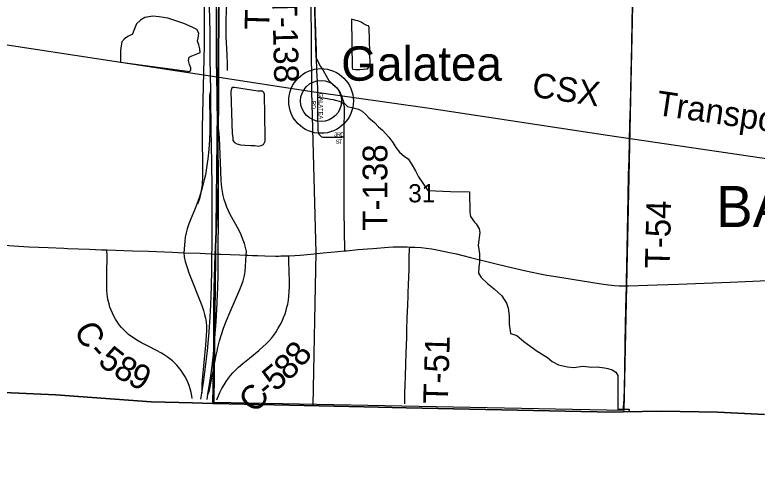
# Model space of a CAD drawing. Extents: x 1443599 to 1910620, y 1028088 to 1361369.
# Drawn here: x 1649524 to 1658538, y 1154990 to 1160667 of the extents above; entities that cross this region are included whole.
import ezdxf

# ---------------------------------------------------------------- set-up
doc = ezdxf.new("R2010")
doc.units = 0
for name, color, linetype in [('GM_X_Adjacent_County', 7, 'Continuous'), ('GM_X_Corporation_Text', 7, 'Continuous'), ('GM_X_County', 7, 'Continuous'), ('GM_X_County_Road', 7, 'Continuous'), ('GM_X_County_Road_Text', 7, 'Continuous'), ('GM_X_Interchange_Ramps', 7, 'Continuous'), ('GM_X_Interstate_Route', 7, 'Continuous'), ('GM_X_Minor_Lake', 7, 'Continuous'), ('GM_X_Minor_River', 7, 'Continuous'), ('GM_X_Rail_Line', 7, 'Continuous'), ('GM_X_Rail_Line_Text', 7, 'Continuous'), ('GM_X_Section', 7, 'Continuous'), ('GM_X_Section_Text', 7, 'Continuous'), ('GM_X_State_Route', 7, 'Continuous'), ('GM_X_Township', 7, 'Continuous'), ('GM_X_Township_Road', 7, 'Continuous'), ('GM_X_Township_Road_Text', 7, 'Continuous'), ('GM_X_Township_Subdivision', 7, 'Continuous'), ('GM_X_Township_Subdivision_Text', 7, 'Continuous'), ('GM_X_Unincorporated', 7, 'Continuous'), ('GM_X_Unincorporated_Location', 7, 'Continuous'), ('GM_X_Unincorporated_Text', 7, 'Continuous')]:
    doc.layers.add(name, color=color, linetype=linetype)

msp = doc.modelspace()

# ---------------------------------------------------------------- linework, layer by layer
at = {"layer": 'GM_X_Adjacent_County'}
msp.add_lwpolyline([(1631321.7, 1156526.4), (1635964.6, 1156489.9), (1636394.3, 1156486.5), (1639893.6, 1156408.7), (1641054, 1156382.8), (1641985.5, 1156362.1), (1643814, 1156287.4), (1643986.6, 1156280.4), (1645977.2, 1156199.2), (1648123.1, 1156134), (1650022.7, 1156050.6), (1651177.8, 1155965), (1651682.5, 1155953.3), (1651801.4, 1155950.6), (1651929.8, 1155947.6), (1651945.1, 1155947.3), (1653765.2, 1155905.3), (1654275.8, 1155894.5), (1656788.7, 1155841.5), (1656910.1, 1155843.6), (1657377.2, 1155851.8), (1658061.8, 1155840.1), (1658626.2, 1155812.7)], dxfattribs=at)
at = {"layer": 'GM_X_County'}
msp.add_lwpolyline([(1658626.2, 1155812.7), (1658061.8, 1155840.1), (1657377.2, 1155851.8), (1656910.1, 1155843.6), (1656788.7, 1155841.5), (1654275.8, 1155894.5), (1653765.2, 1155905.3), (1651945.1, 1155947.3), (1651929.8, 1155947.6), (1651801.4, 1155950.6), (1651682.5, 1155953.3), (1651177.8, 1155965), (1650022.7, 1156050.6), (1648123.1, 1156134), (1645977.2, 1156199.2), (1643986.6, 1156280.4), (1643814, 1156287.4), (1641985.5, 1156362.1), (1641054, 1156382.8), (1639893.6, 1156408.7), (1636394.3, 1156486.5), (1635964.6, 1156489.9), (1631321.7, 1156526.4)], dxfattribs=at)
at = {"layer": 'GM_X_County_Road'}
for points in [[(1650643, 1157427.7), (1650642.7, 1157563.4), (1650644.3, 1157702.8), (1650643.8, 1157744), (1650643.1, 1157811.6)], [(1651977.1, 1155989.1), (1651983.9, 1156009.9), (1651995.9, 1156040.7), (1652013.3, 1156078), (1652039.8, 1156129.2), (1652064.2, 1156172.1), (1652090.9, 1156213.7), (1652119.3, 1156254.1), (1652144.6, 1156286.6), (1652171.6, 1156317.8), (1652200.1, 1156347.5), (1652241.9, 1156387.1), (1652291.2, 1156430.5), (1652373.6, 1156498.3), (1652488.3, 1156590.9), (1652537.3, 1156634.1), (1652578.8, 1156673.4), (1652612.8, 1156708.6), (1652645, 1156745.4), (1652670.1, 1156777.5), (1652698, 1156817.6), (1652723.8, 1156859.2), (1652747.4, 1156902), (1652769, 1156945.9), (1652788.5, 1156990.8), (1652805.8, 1157036.5), (1652818.4, 1157075.3), (1652829.2, 1157114.5), (1652838.1, 1157154.3), (1652846.2, 1157202.5), (1652852.2, 1157251.1), (1652856.6, 1157308.1), (1652858.7, 1157365.2), (1652858.8, 1157430.6), (1652855.1, 1157545.1), (1652850.3, 1157676.2), (1652850.1, 1157741)], [(1651678.4, 1156007), (1651673, 1156037.3), (1651664.5, 1156077.7), (1651651.9, 1156125.6), (1651639.2, 1156164.8), (1651624.3, 1156203.4), (1651607, 1156240.9), (1651587.4, 1156277.3), (1651566, 1156312.5), (1651542.7, 1156346.6), (1651512.5, 1156386), (1651490.9, 1156411), (1651468.1, 1156434.9), (1651437.9, 1156463.1), (1651406.1, 1156489.5), (1651372.9, 1156514.1), (1651338.6, 1156537), (1651303.3, 1156558.3), (1651245.5, 1156589.8), (1651143.3, 1156642.4), (1651055.8, 1156687.3), (1651005.9, 1156715.4), (1650964.4, 1156741.4), (1650931.1, 1156764.9), (1650905.6, 1156785), (1650881, 1156806.4), (1650851.7, 1156834.7), (1650818.4, 1156870.6), (1650792.7, 1156902.1), (1650769, 1156935.3), (1650747.3, 1156969.8), (1650727.4, 1157005.3), (1650709.5, 1157041.9), (1650693.7, 1157079.5), (1650679.8, 1157117.8), (1650667.9, 1157156.8), (1650658.1, 1157196.4), (1650650.6, 1157236.4), (1650645.7, 1157276.8), (1650643.3, 1157317.4), (1650643.2, 1157366.5), (1650643, 1157427.7)]]:
    msp.add_lwpolyline(points, dxfattribs=at)
at = {"layer": 'GM_X_Interchange_Ramps'}
for points in [[(1651902.3, 1159748.6), (1651897.5, 1159730.1), (1651891.6, 1159707.8), (1651888.4, 1159686.3), (1651886.4, 1159659.1), (1651887.3, 1159622.2), (1651891.3, 1159410), (1651890.8, 1159262), (1651886.4, 1159146.9), (1651878.5, 1159032.1), (1651867.1, 1158917.6), (1651856.6, 1158836), (1651839.6, 1158725), (1651825.3, 1158664.3), (1651811.8, 1158614), (1651790.4, 1158538), (1651761.8, 1158443.6), (1651734.6, 1158367.5), (1651704.8, 1158292.5), (1651659.5, 1158187.3), (1651636.5, 1158126.9), (1651615.9, 1158066.4), (1651603.4, 1158017.7), (1651594.6, 1157968.2), (1651588.9, 1157918.3), (1651576, 1157776.8)], [(1652334.4, 1157746.9), (1652335.9, 1157793.8), (1652333.6, 1157810.1), (1652326.2, 1157842), (1652312.1, 1157889.2), (1652290.2, 1157951.1), (1652271.3, 1157996.6), (1652242.7, 1158055.7), (1652140.6, 1158243.1), (1652118.5, 1158287.2), (1652098.5, 1158332.1), (1652081.2, 1158378.2), (1652066.3, 1158425.2), (1652054.2, 1158472.9), (1652044.8, 1158521.2), (1652037.7, 1158570), (1652030.6, 1158651.8), (1652025, 1158766.5), (1652009, 1159172.8), (1652005.9, 1159222), (1652002.5, 1159257.6), (1651997.2, 1159295), (1651986.8, 1159348)], [(1651576, 1157776.8), (1651579.2, 1157727.7), (1651591.9, 1157672.3), (1651611.2, 1157609.9), (1651638.8, 1157533), (1651794.3, 1157137.4), (1651815.8, 1157075.6), (1651828.9, 1157028.5), (1651838.8, 1156980.4), (1651845.7, 1156931.9), (1651849.7, 1156883.1), (1651850.6, 1156834.1), (1651848.3, 1156768.7), (1651839.7, 1156654.5), (1651798.1, 1156231.6), (1651795.1, 1156190.3), (1651793.4, 1156137.4), (1651795, 1156071.2)], [(1651869, 1156056.6), (1651880.5, 1156081.8), (1651885.7, 1156094.9), (1651889.8, 1156109.2), (1651945.4, 1156402.3), (1651969.7, 1156531), (1651980.6, 1156580.5), (1651990.8, 1156627), (1652011.1, 1156706.2), (1652034.2, 1156784.8), (1652060.1, 1156862.5), (1652094.3, 1156954.5), (1652138, 1157060.5), (1652255.8, 1157330.7), (1652280.4, 1157391.4), (1652296.6, 1157437.7), (1652305.6, 1157469.2), (1652312.7, 1157501.1), (1652320.6, 1157549.5), (1652326.4, 1157614.7), (1652330.4, 1157680.1), (1652334.4, 1157746.9)]]:
    msp.add_lwpolyline(points, dxfattribs=at)
at = {"layer": 'GM_X_Interstate_Route'}
for points in [[(1651974.6, 1160049.3), (1651973.4, 1160186.6), (1651972, 1160498.4), (1651971.2, 1160728.2), (1651973.4, 1161039.9), (1651974.7, 1161285.4), (1651975.2, 1161368.1), (1651976.4, 1161473.3), (1651982.7, 1162040.8), (1651983.8, 1162352.5), (1651985.4, 1162591.9)], [(1651784.4, 1155999.6), (1651795, 1156071.2), (1651817.5, 1156227.3), (1651839.9, 1156389.9), (1651862.1, 1156585.7), (1651883.5, 1156814.6), (1651897.4, 1156994.7), (1651905.8, 1157142.3), (1651913.7, 1157372), (1651917, 1157569), (1651916.9, 1157733), (1651917.6, 1157764.6), (1651918.6, 1157815.1), (1651920.5, 1158077.6), (1651921.9, 1158291.1), (1651920.1, 1158570.1), (1651914.7, 1158865.4), (1651910, 1159292), (1651903.1, 1159653), (1651902.3, 1159748.6), (1651900.9, 1159932), (1651898.1, 1160145.4), (1651894.2, 1160457.1), (1651889.6, 1160768.9)], [(1651997, 1158390.5), (1651997.2, 1158496.6), (1651993.5, 1158923.1), (1651986.8, 1159348), (1651986.5, 1159366.1), (1651982.5, 1159628.6), (1651975.2, 1159973.2), (1651974.6, 1160049.3)], [(1651994.4, 1157718.7), (1651994.4, 1157725.3), (1651994.6, 1157761.2), (1651995.3, 1157922.3), (1651996.5, 1158070), (1651997, 1158390.5)], [(1651987.1, 1157274.4), (1651990.1, 1157348.1), (1651993.3, 1157528.5), (1651994.4, 1157718.7)], [(1651858.7, 1155994.9), (1651869, 1156056.6), (1651899.3, 1156253.4), (1651919.1, 1156399.7), (1651935.5, 1156546.3), (1651958.7, 1156791.3), (1651969.8, 1156938.5), (1651982.9, 1157167.8), (1651987.1, 1157274.4)]]:
    msp.add_lwpolyline(points, dxfattribs=at)
at = {"layer": 'GM_X_Minor_Lake'}
for p, q in [((1653613.2, 1160613.1), (1653620.3, 1160023.4)), ((1650806.1, 1160093.6), (1651651.3, 1159979.3)), ((1652476.7, 1159741), (1652191, 1159783.1))]:
    msp.add_line(p, q, dxfattribs=at)
for points in [[(1651651.3, 1159979.3), (1651661.6, 1159997.2), (1651660, 1160023.3), (1651646.6, 1160063.6), (1651633.4, 1160113.9), (1651639.9, 1160151.9), (1651674.2, 1160167.5), (1651718.5, 1160184.9), (1651775, 1160210.2), (1651771.6, 1160254.3), (1651758.3, 1160302.6), (1651743, 1160349), (1651749.5, 1160383), (1651760.5, 1160443), (1651735.1, 1160489.5), (1651679.5, 1160518.3), (1651576.1, 1160563.9), (1651492.4, 1160589.2), (1651380.8, 1160628.9), (1651274.9, 1160642.4), (1651199, 1160651.5), (1651102.6, 1160636.9), (1651052.1, 1160603.5), (1651001.3, 1160556.1), (1650976.3, 1160496.3), (1650961.7, 1160456.4), (1650951.4, 1160432.5), (1650894.9, 1160403.2), (1650854.4, 1160375.7), (1650821.8, 1160340.1), (1650815.1, 1160292), (1650808.2, 1160236), (1650806.1, 1160093.6)], [(1653620.3, 1160023.4), (1653626.1, 1160007.3), (1653662.1, 1160002.8), (1653714, 1160004), (1653756.2, 1160007.5), (1653806.4, 1160012.8), (1653832.8, 1160040.5), (1653839.1, 1160060.4), (1653826, 1160513.8), (1653818.2, 1160532), (1653800.3, 1160536.2), (1653766.5, 1160552.8), (1653730.8, 1160579.3), (1653691, 1160593.9), (1653665.1, 1160600.3), (1653613.2, 1160613.1)], [(1652191, 1159783.1), (1652173, 1159783.4), (1652156.8, 1159771.6), (1652146.3, 1159737.6), (1652164.5, 1159222), (1652171.9, 1159177.8), (1652173.3, 1159139.7), (1652191.3, 1159116), (1652218.8, 1159100.9), (1652262.6, 1159086.3), (1652320.7, 1159085.4), (1652390.7, 1159080.4), (1652438.7, 1159081.8), (1652482.7, 1159073.1), (1652516.8, 1159078.6), (1652543, 1159092.3), (1652563.6, 1159132.1), (1652564.5, 1159186.2), (1652556.2, 1159701.7), (1652547.5, 1159724.3), (1652530.7, 1159738.2), (1652476.7, 1159741)]]:
    msp.add_lwpolyline(points, dxfattribs=at)
at = {"layer": 'GM_X_Minor_River'}
for points in [[(1651631.1, 1165306.8), (1651741.3, 1164983.8), (1651761.2, 1164468.2), (1651757.1, 1163998.8), (1651606.7, 1163615.7), (1651456.4, 1163246.7), (1651446.1, 1162337.9), (1651434, 1161690), (1651427.9, 1161220.6), (1651824.5, 1161196.5), (1651822.3, 1160299.7), (1651800.1, 1159298.6), (1651804.1, 1158702.8), (1651800, 1158602.5), (1651784, 1158510.2), (1651768, 1158431.9), (1651743.9, 1158365.7)], [(1653150.7, 1161142.1), (1653178.5, 1160147.1), (1653234.6, 1160038.8), (1653264.7, 1160000.6), (1653304.7, 1159924.4), (1653338.8, 1159870.2), (1653380.8, 1159826.1), (1653428.9, 1159784), (1653469, 1159731.8), (1653497, 1159665.6), (1653521, 1159597.4), (1653565.1, 1159553.2), (1653631.2, 1159539.2), (1653699.3, 1159521.1), (1653743.4, 1159497), (1653787.4, 1159454.9), (1653823.5, 1159414.8), (1653891.6, 1159358.6), (1653939.7, 1159306.4), (1653989.7, 1159266.3), (1654067.8, 1159180), (1654113.9, 1159115.8), (1654150, 1159057.6), (1654196, 1158999.4), (1654256.1, 1158945.3), (1654302.2, 1158917.2), (1654338.3, 1158861), (1654388.3, 1158772.7), (1654424.4, 1158698.5), (1654538.5, 1158533.9), (1654813, 1158521.9), (1655043.4, 1158517.8), (1655051.3, 1158265), (1655057.4, 1158216.9), (1655105.4, 1158146.6), (1655127.5, 1158126.6), (1655163.5, 1158066.4), (1655171.5, 1158022.2), (1655149.5, 1157867.8), (1655165.5, 1157763.4), (1655165.5, 1157663.1), (1655159.4, 1157606.9), (1655153.4, 1157528.7), (1655187.5, 1157476.5), (1655265.6, 1157402.3), (1655345.7, 1157340.1), (1655439.9, 1157253.8), (1655494, 1157165.5), (1655516, 1157103.3), (1655526, 1157009), (1655526, 1156910.7), (1655538, 1156826.4), (1655542, 1156796.3), (1655620.1, 1156772.2), (1655706.3, 1156698), (1655794.4, 1156635.8), (1655866.5, 1156579.6), (1655990.7, 1156503.3), (1656050.8, 1156457.1), (1656126.9, 1156417), (1656235.1, 1156390.9), (1656313.2, 1156384.9), (1656421.4, 1156398.9), (1656529.6, 1156386.9), (1656593.7, 1156390.9), (1656685.9, 1156380.8), (1656725.9, 1156370.8), (1656778, 1156352.7), (1656824.1, 1156324.6), (1656848.1, 1156284.5), (1656848.1, 1156222.3), (1656846.1, 1155877.2), (1656982.3, 1155875.2), (1656981.1, 1155847.1)]]:
    msp.add_lwpolyline(points, dxfattribs=at)
at = {"layer": 'GM_X_Rail_Line'}
for points in [[(1653131.7, 1159734.3), (1653131.5, 1159774.4), (1653117.5, 1161384.9), (1653128.4, 1163893.8), (1653262.4, 1169152.8), (1653341.6, 1175752.4), (1653359.9, 1180304.5), (1653421.3, 1187177.3), (1653422.3, 1187382.1)], [(1645299.4, 1160898), (1647993, 1160519.8), (1651978.5, 1159912.5)], [(1651978.5, 1159912.5), (1653131.7, 1159734.3)], [(1653147.8, 1155927.1), (1653183.2, 1157781.6), (1653131.7, 1159734.3)], [(1653131.7, 1159734.3), (1654559.8, 1159532.2), (1656720, 1159206.3), (1661518.7, 1158502.4), (1663430.3, 1158232.7), (1665610.5, 1157902.5), (1670331.1, 1157208.4), (1674785.3, 1156557.2), (1678092.3, 1156076.4), (1685476.1, 1154990)]]:
    msp.add_lwpolyline(points, dxfattribs=at)
at = {"layer": 'GM_X_Section'}
msp.add_lwpolyline([(1657034.3, 1161164.9), (1656920.5, 1155860.4), (1651946.1, 1155956.1), (1652006.2, 1161276.9)], close=True, dxfattribs=at)
at = {"layer": 'GM_X_State_Route'}
for points in [[(1649279.5, 1157881.9), (1649305.8, 1157879.4), (1649449.8, 1157866.7), (1649694.2, 1157849.8), (1649930.7, 1157838.9), (1650119.3, 1157831.9), (1650164.6, 1157830.1)], [(1650164.6, 1157830.1), (1650430.4, 1157819.6)], [(1650430.4, 1157819.6), (1650576.2, 1157813.8), (1650643.1, 1157811.6), (1650951.4, 1157801.4), (1651147.3, 1157795.2), (1651440.2, 1157782.6), (1651576, 1157776.8), (1651775.2, 1157770.5), (1651834.3, 1157768.3), (1651835.7, 1157768.3)], [(1651835.7, 1157768.3), (1651917.6, 1157764.6), (1651994.6, 1157761.2), (1652024.9, 1157759.9), (1652252.2, 1157749.9), (1652334.4, 1157746.9)], [(1652850.1, 1157741), (1652924.5, 1157744.9), (1652990.4, 1157749.6), (1653119.6, 1157760.4), (1653195.6, 1157766.7), (1653231.2, 1157771.2), (1653266.9, 1157774.9), (1653361.6, 1157784.1), (1653531.7, 1157800.5), (1653551.1, 1157802.3), (1653694.9, 1157816.2), (1653806.1, 1157825)], [(1653806.1, 1157825), (1653871.5, 1157830.1), (1654061.3, 1157845.4), (1654120.2, 1157848.1), (1654181.7, 1157849.4), (1654290.4, 1157847.7), (1654319, 1157846.6), (1654382.2, 1157844.3), (1654457.4, 1157839.3), (1654519.2, 1157833), (1654587.2, 1157823.2), (1654667.9, 1157808.8), (1654803, 1157781.7), (1654886.2, 1157763.2), (1654962.5, 1157744), (1655058, 1157720), (1655351.1, 1157647.1), (1655501.3, 1157611.5), (1655728.5, 1157559.2), (1655882.5, 1157525.5), (1655982.5, 1157506), (1656118.6, 1157483), (1656293.8, 1157456), (1656517.2, 1157418.6), (1656643.8, 1157399.1), (1656735, 1157386.9), (1656807.1, 1157379.8), (1656863, 1157376.3), (1656950.1, 1157375.5), (1656977.4, 1157376.2), (1657322.4, 1157385.3), (1657585.1, 1157393.4), (1657897, 1157406.6), (1658209, 1157421.3), (1658668.8, 1157439.2)], [(1652334.4, 1157746.9), (1652356.7, 1157746), (1652412.3, 1157743.4), (1652470.5, 1157742.1), (1652561.1, 1157739.2), (1652689.1, 1157736.7), (1652728.6, 1157737.2), (1652754.9, 1157737.8), (1652850.1, 1157741)]]:
    msp.add_lwpolyline(points, dxfattribs=at)
at = {"layer": 'GM_X_Township'}
for points in [[(1652041.9, 1171813.2), (1652030.8, 1166476.2), (1652008.3, 1163866.7), (1651998.2, 1162695.7), (1651998.9, 1162185.8), (1652000.1, 1161249), (1651996.4, 1159520.9), (1651990.3, 1159208.4), (1651994.9, 1158602.7), (1651958, 1157753.6), (1651943.2, 1157343), (1651941.2, 1157133.4), (1651940.5, 1156563.6), (1651929.8, 1155947.6), (1651801.4, 1155950.6), (1651682.5, 1155953.3), (1651177.8, 1155965), (1650022.7, 1156050.6), (1648123.1, 1156134)], [(1658626.2, 1155812.7), (1658061.8, 1155840.1), (1657377.2, 1155851.8), (1656910.1, 1155843.6), (1656788.7, 1155841.5), (1654275.8, 1155894.5), (1653765.2, 1155905.3), (1651945.1, 1155947.3), (1651929.8, 1155947.6), (1651940.5, 1156563.6), (1651941.2, 1157133.4), (1651943.2, 1157343), (1651958, 1157753.6), (1651994.9, 1158602.7), (1651990.3, 1159208.4), (1651996.4, 1159520.9), (1652000.1, 1161249), (1651998.9, 1162185.8), (1651998.2, 1162695.7), (1652008.3, 1163866.7), (1652030.8, 1166476.2), (1652041.9, 1171813.2)]]:
    msp.add_lwpolyline(points, dxfattribs=at)
at = {"layer": 'GM_X_Township_Road'}
for points in [[(1653205.2, 1159663.4), (1653205.6, 1159685), (1653203.5, 1159782.8), (1653200.4, 1159839.9), (1653195.1, 1159938.1), (1653193.5, 1159970.8), (1653190.1, 1160044.6), (1653187.7, 1160101.9), (1653187.5, 1160224.3), (1653184.2, 1160338.3), (1653180.2, 1160439.5), (1653179.5, 1160483.1), (1653176.7, 1160557.6), (1653172.3, 1160693.5), (1653167, 1160874.6), (1653160.3, 1161068.6), (1653158.1, 1161165.1), (1653157.5, 1161214.3), (1653157.1, 1161239.6)], [(1656950.1, 1157375.5), (1656951.2, 1157426.1), (1656958.6, 1157819.8), (1656971.8, 1158459.6), (1656977.8, 1158722), (1656982.7, 1158918.8), (1656987.9, 1159132), (1656993.1, 1159345.2), (1656998.6, 1159558.4), (1657008.8, 1159952), (1657015.6, 1160296.5), (1657021.7, 1160591.8), (1657029.5, 1160936.2), (1657032.2, 1161116.6), (1657032.7, 1161165.8)], [(1652108, 1159989.9), (1652105.3, 1160063.8), (1652101.2, 1160186.9), (1652090.6, 1160400.2), (1652089.4, 1160465.9), (1652091, 1160580.9), (1652095.1, 1160736.9), (1652096.8, 1160781.5)], [(1653523.1, 1159569.8), (1653518.4, 1159578.1), (1653512.8, 1159585.4), (1653507.3, 1159591.5), (1653501.4, 1159597.1), (1653495, 1159602), (1653487.7, 1159606.6), (1653480.9, 1159610), (1653467.5, 1159615), (1653451.9, 1159619.5), (1653435, 1159624.2), (1653419.6, 1159628.1), (1653395.9, 1159633.2), (1653359.2, 1159640.5), (1653315.2, 1159648), (1653267.1, 1159655.7), (1653226.8, 1159660.7), (1653205.2, 1159663.4)], [(1653521.6, 1159179.3), (1653521.5, 1159195.1), (1653521.8, 1159318.1), (1653526.1, 1159473.8), (1653526.7, 1159539.1), (1653526.1, 1159551.7), (1653525, 1159560.5), (1653523.1, 1159569.8)], [(1653523.5, 1158751), (1653523.6, 1158785.5), (1653525.1, 1158916.7), (1653524.6, 1158998.6), (1653523.5, 1159104.8), (1653521.9, 1159145.3), (1653521.6, 1159179.3)], [(1653531.7, 1157800.5), (1653531, 1157842.7), (1653528.4, 1158006.6), (1653525.1, 1158318.2), (1653522.7, 1158474), (1653523.5, 1158703.5), (1653523.5, 1158751)], [(1654258.6, 1155941.5), (1654259.5, 1155989.3), (1654261.7, 1156064.3), (1654264.9, 1156180.1), (1654268.1, 1156270.2), (1654271.7, 1156426), (1654275.8, 1156557.2), (1654282.7, 1156745.7), (1654285.1, 1156844), (1654289, 1156983.4), (1654295.2, 1157139.1), (1654299.2, 1157253.8), (1654299.7, 1157294.8), (1654302.9, 1157384.1), (1654310.9, 1157580.8), (1654314.5, 1157728.7), (1654318, 1157822.5), (1654319, 1157846.6)], [(1656911.4, 1155874.5), (1656914.4, 1155898.3), (1656919.3, 1155951.3), (1656922.7, 1155999.2), (1656927.5, 1156130.2), (1656931.1, 1156343.4), (1656935.4, 1156688), (1656943.9, 1157098.1), (1656950.1, 1157375.5)]]:
    msp.add_lwpolyline(points, dxfattribs=at)
at = {"layer": 'GM_X_Township_Subdivision'}
for points in [[(1653227.9, 1159204.9), (1653221.8, 1159214.8), (1653218, 1159223), (1653214.1, 1159233.4), (1653211.6, 1159243.2), (1653207.9, 1159267.9), (1653206.8, 1159282.8), (1653205.7, 1159310.9), (1653204.5, 1159408.2), (1653203.7, 1159464.9), (1653204, 1159503.6), (1653204.3, 1159547.1), (1653204.5, 1159580.5), (1653204.8, 1159614.4), (1653205.2, 1159663.4)], [(1653521.6, 1159179.3), (1653494.7, 1159179), (1653455.2, 1159178.6), (1653414.3, 1159178.6), (1653348.1, 1159177), (1653307.2, 1159176.2), (1653282.7, 1159177), (1653268.1, 1159178.9), (1653257.5, 1159181.6), (1653250.1, 1159185.1), (1653243.1, 1159189.4), (1653234.1, 1159197.6), (1653227.9, 1159204.9)]]:
    msp.add_lwpolyline(points, dxfattribs=at)
at = {"layer": 'GM_X_Unincorporated'}
for radius in [392.8, 249]:
    msp.add_circle((1653242.4, 1159620.7), radius, dxfattribs=at)
at = {"layer": 'GM_X_Unincorporated_Location'}
msp.add_line((1653242.4, 1159620.7), (1653242.4, 1159620.7), dxfattribs=at)

# ---------------------------------------------------------------- texts
at = {"layer": 'GM_X_Corporation_Text'}
msp.add_text('BAIRDSTOWN', height=500, rotation=0.00001, dxfattribs=at).set_placement((1658038.8, 1158088.4))
at = {"layer": 'GM_X_County_Road_Text'}
for s, rotation, p in [('C', 298.08374, (1650234.8, 1156843.7)), ('8', 51.78068, (1653011.8, 1156374.3)), ('-', 312.72996, (1650399.2, 1156558.2)), ('5', 321.55071, (1650519.7, 1156433.4)), ('8', 329.78212, (1650703.3, 1156292)), ('8', 43.01807, (1652842.8, 1156211.4)), ('9', 333.10909, (1650879.7, 1156189.9)), ('5', 39.49041, (1652685, 1156080.6)), ('C', 54.93395, (1652464.4, 1155814.4)), ('-', 40.59113, (1652592.6, 1156001.4))]:
    msp.add_text(s, height=300, rotation=rotation, dxfattribs=at).set_placement(p)
at = {"layer": 'GM_X_Rail_Line_Text'}
for s, rotation, p in [('CSX', 351.49556, (1655792, 1159675)), ('Transportation,', 351.61232, (1657300.8, 1159452.5))]:
    msp.add_text(s, height=299, rotation=rotation, dxfattribs=at).set_placement(p)
at = {"layer": 'GM_X_Section_Text'}
msp.add_text('31', height=221, rotation=0.00001, dxfattribs=at).set_placement((1654301.2, 1158389.4))
at = {"layer": 'GM_X_Township_Road_Text'}
for s, rotation, p in [('T-138', 271.40259, (1652649.8, 1160884.9)), ('T', 88.29836, (1652612.9, 1160481.7)), ('T-138', 90, (1654047.5, 1158045.9)), ('T-54', 88.58635, (1657475, 1157584.2)), ('T-51', 88.25039, (1654782.2, 1155938.6))]:
    msp.add_text(s, height=300, rotation=rotation, dxfattribs=at).set_placement(p)
at = {"layer": 'GM_X_Township_Subdivision_Text'}
for s, rotation, p in [('GALATEA', 270, (1653215, 1159717.9)), ('RD', 270, (1653130, 1159621.1)), ('3', 355.87434, (1653400, 1159190.4)), ('R', 359.11041, (1653433.8, 1159188.1)), ('D', 3.73928, (1653477.8, 1159187.6)), ('S', 1.18837, (1653421.5, 1159100.1)), ('T', 5.65148, (1653461, 1159101))]:
    msp.add_text(s, height=50, rotation=rotation, dxfattribs=at).set_placement(p)
at = {"layer": 'GM_X_Unincorporated_Text'}
msp.add_text('Galatea', height=417, rotation=0.00001, dxfattribs=at).set_placement((1653487.2, 1159867.2))

doc.saveas('drawing.dxf')
